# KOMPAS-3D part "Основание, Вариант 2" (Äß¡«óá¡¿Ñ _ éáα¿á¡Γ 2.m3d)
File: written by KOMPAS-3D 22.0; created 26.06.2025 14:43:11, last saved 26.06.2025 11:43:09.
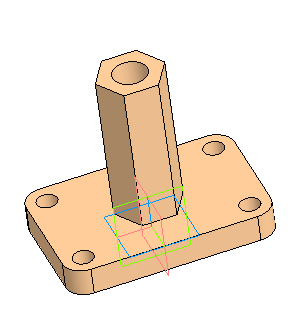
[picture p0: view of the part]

Document properties: Автор: Helen; Полное имя файла: D:\MY\WORK\MPEI\ППЭ_2025-2026\Варианты\Вар 2 СБ\Основание _ Вариант 2.m3d

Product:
- Body: Тело 1
    Масса: 3.618613
- Part/product: Основание  | designation Вариант 2
    Масса: 3.117293

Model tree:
1. Эскиз:1
2. Элемент выдавливания:1
     Расстояние 1 = 20
3. Эскиз:3  (with: Элемент выдавливания:1)
4. Элемент выдавливания:3
     Расстояние 1 = 110
5. Эскиз:4  (with: Элемент выдавливания:1)
6. Элемент выдавливания:4
     Расстояние 2 = 20
7. Массив по сетке:1  (with: Элемент выдавливания:4, Эскиз:4, Элемент выдавливания:1)  (4 pattern instances)
     Шаг 1 = 120; Угол раствора = 90; Шаг 2 = 70
8. Эскиз:5  (with: Элемент выдавливания:3)
9. Элемент выдавливания:5
     Расстояние 2 = 130

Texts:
  Вариант 2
